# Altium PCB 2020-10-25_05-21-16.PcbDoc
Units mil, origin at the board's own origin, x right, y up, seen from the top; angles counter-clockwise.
Board outline 4000 x 2000 mil, 4 copper layers (Top Layer, MidLayer1, MidLayer2, Bottom Layer); 21 components, 14 nets, 69 pads, 67 vias.
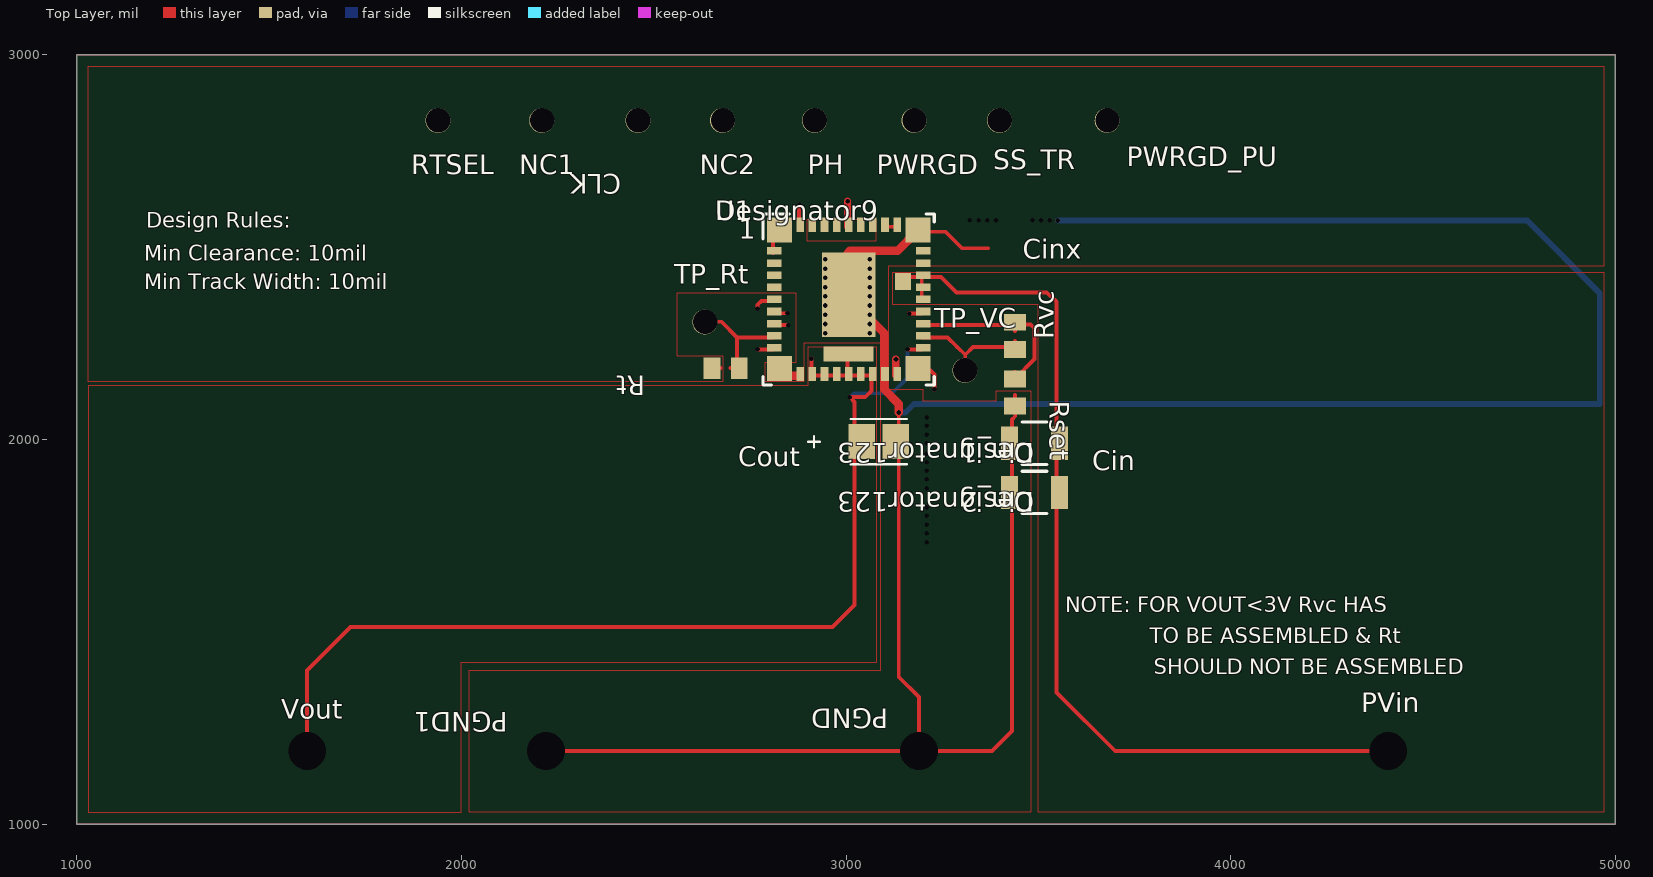
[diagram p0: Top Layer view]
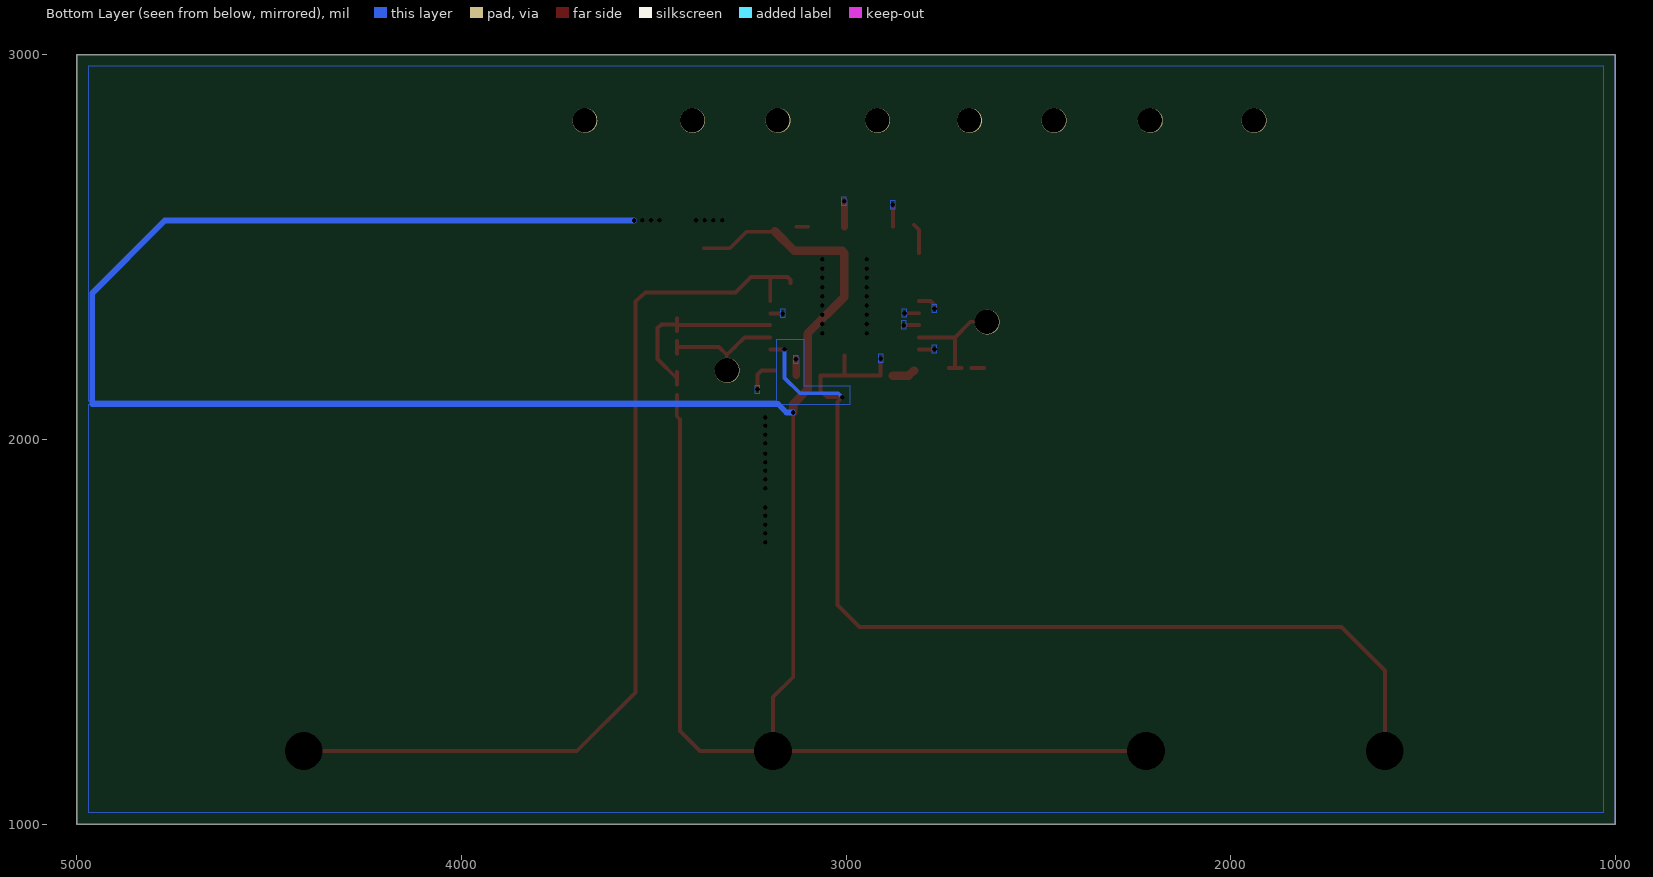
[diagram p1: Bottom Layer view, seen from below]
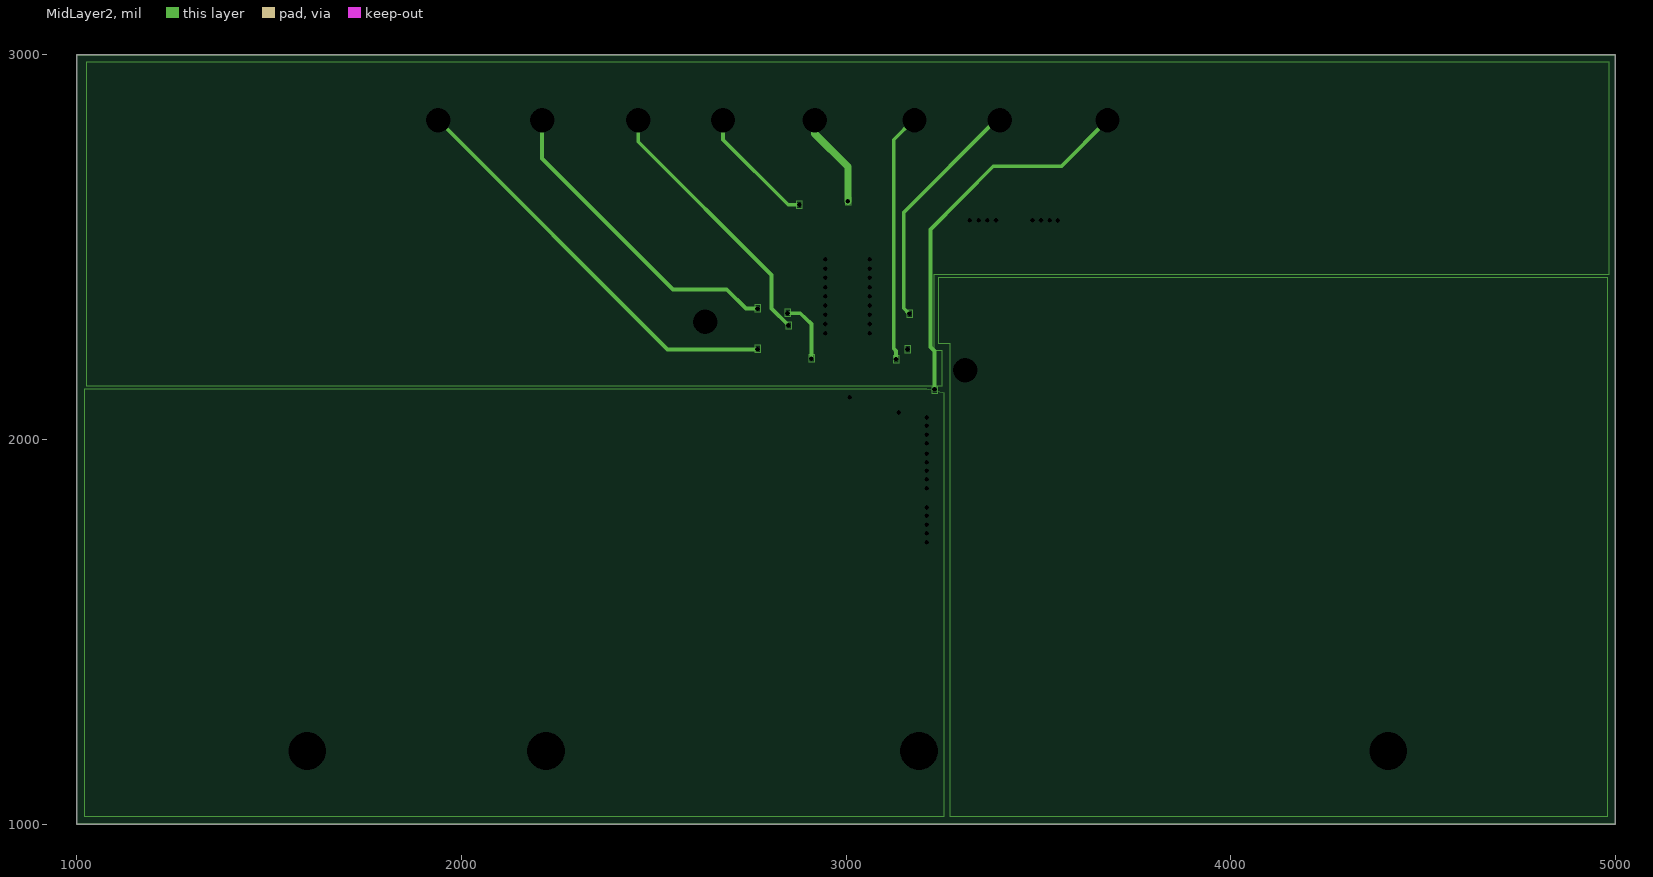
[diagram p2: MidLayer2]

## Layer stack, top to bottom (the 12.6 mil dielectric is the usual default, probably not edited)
Top Layer: signal copper 1.4
Dielectric: core 12.6, FR-4, Dk 4.8
MidLayer1: signal copper 1.4
Dielectric: prepreg 12.6, FR-4, Dk 4.8
MidLayer2: signal copper 1.4
Dielectric: core 12.6, FR-4, Dk 4.8
Bottom Layer: signal copper 1.4

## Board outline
1000,1000 5000,1000 5000,3000 1000,3000

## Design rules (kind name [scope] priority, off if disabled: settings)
PlaneConnect [All] p0: scope1count=1 scope1_0_kind=Board scope1_0_value=Board scope2count=1 scope2_0_kind=Board scope2_0_value=Board commentlength=0 planeconnectstyle=Direct reliefexpansion=20 reliefentries=4 reliefconductorwidth=10 reliefairgap=10
PlaneConnect [All] p1: planeconnectstyle=Direct reliefexpansion=20 reliefentries=4 reliefconductorwidth=10 reliefairgap=10
PolygonConnect [All] p0: scope1count=1 scope1_0_kind=Board scope1_0_value=Board scope2count=1 scope2_0_kind=Board scope2_0_value=Board commentlength=0 connectstyle=Direct reliefconductorwidth=10 reliefentries=4 polygonreliefangle="90 Angle"
PolygonConnect [All] p1: connectstyle=Direct reliefconductorwidth=10 reliefentries=4 polygonreliefangle="90 Angle"

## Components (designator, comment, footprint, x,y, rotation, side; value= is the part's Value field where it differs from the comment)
Cin_1 "" 1210_280 3490,1990 r180 top
Cin_2 "" 1210_280 3490,1862 r180 top
CLK "" TP-1502 2459,2829 r180 top
Cout "" 3528-21 3085,1994 r0 top
NC1 "" TP-1502 2209,2829 r0 top
NC2 "" TP-1502 2679,2829 r0 top
PGND "" TP-1502 3189,1189 r180 top
PGND1 "" TP-1502 2220,1189 r180 top
PH "" TP-1502 2918,2829 r0 top
PVin "" TP-1502 4409,1189 r0 top
PWRGD "" TP-1502 3177,2829 r0 top
PWRGD_PU "" TP-1502 3679,2829 r0 top
Rset "" 0805 3439,2122 r270 top
Rt "" 0805 2687,2185 r180 top
RTSEL "" TP-1502 1939,2829 r0 top
Rvc "" 0805 3439,2269 r90 top
SS_TR "" TP-1502 3399,2829 r0 top
TP_Rt "" TP-1502 2633,2305 r0 top
TP_VC "" TP-1502 3309,2179 r0 top
U1 "" RVQ0043A 3007,2364 r0 top
Vout "" TP-1502 1598,1189 r0 top

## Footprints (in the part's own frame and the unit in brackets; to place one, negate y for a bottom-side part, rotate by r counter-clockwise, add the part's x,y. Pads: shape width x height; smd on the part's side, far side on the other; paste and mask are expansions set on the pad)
0805 [mil]
  rect 44x57 smd: 1(-35.5,0) 2(35.5,0)
1210_280 [mm]
  rect 1.1x2.2 smd: 1(-1.65,0) 2(1.65,0)
  silkscreen extent -0.84,-1.4 0.84,1.4
3528-21 [mil]
  rect 69x91 smd: 1(-44.5,0) 2(44.5,0)
  silkscreen extent -183,-59 73,59
RVQ0043A [mm]
  rect 1.65x1.65 smd: 1(-4.575,4.575) 11(-4.575,-4.575) 21(4.575,-4.575) 31(4.575,4.575)
  rect 0.95x0.5 smd: 2(-4.925,3.2) 3(-4.925,2.4) 4(-4.925,1.6) 5(-4.925,0.8) 6(-4.925,0) 7(-4.925,-0.8) 8(-4.925,-1.6) 9(-4.925,-2.4) 10(-4.925,-3.2) 22(4.925,-3.2) 23(4.925,-2.4) 24(4.925,-1.6) 25(4.925,-0.8) 26(4.925,0) 27(4.925,0.8) 28(4.925,1.6) 29(4.925,2.4) 30(4.925,3.2)
  rect 0.5x0.95 smd: 12(-3.2,-4.925) 13(-2.4,-4.925) 14(-1.6,-4.925) 15(-0.8,-4.925) 16(0,-4.925) 17(0.8,-4.925) 18(1.6,-4.925) 19(2.4,-4.925) 20(3.2,-4.925) 32(3.2,4.925) 33(2.4,4.925) 34(1.6,4.925) 35(0.8,4.925) 36(0,4.925) 37(-0.8,4.925) 38(-1.6,4.925) 39(-2.4,4.925) 40(-3.2,4.925)
  rect 3.55x5.6 smd: 41(0,0.3)
  rect 1.05x1.12 smd: 42(3.575,1.187)
  rect 3.3x1 smd: 43(0,-3.6)
  silkscreen extent -5.65,-5.65 5.65,5.65
TP-1502 [mil]
  round 65 / inner round 0 / far side round 65 hole 32: 1(0,0)

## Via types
v1: diameter 0, hole 12, Top Layer to Bottom Layer, 53 vias
v2: diameter 0, hole 63, Top Layer to Bottom Layer, 10 vias
v3: diameter 0, hole 98, Top Layer to Bottom Layer, 4 vias

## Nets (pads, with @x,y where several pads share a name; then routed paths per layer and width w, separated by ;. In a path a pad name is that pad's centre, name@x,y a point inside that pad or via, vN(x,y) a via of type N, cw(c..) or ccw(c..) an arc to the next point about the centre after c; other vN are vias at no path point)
0: Cin_1.2 Cin_2.2 Cout.2 PGND1.1 PGND.1 Rset.2 Rt.2 U1.1 U1.2 U1.3 U1.4 U1.5 U1.11 U1.12 U1.19 U1.29 U1.30 U1.31 U1.32 U1.33 U1.41 | length 7717.2
  Top Layer w10: v3(2220,1190) v3(3190,1190) ; Rt.2@2641,2185.5 2674,2185.5 ; U1.2@2810,2485 2810,2545 U1.1@2823,2558 ; U1.33@3098,2553 U1.32@3129,2553 ; v1(3137,2070) 3137,1960 3137,1382 3190,1330 v3(3190,1190) ; U1.31@3184,2540 3259,2540 3302,2497 3370,2497 ; Rset.2@3439.5,2083 3439.5,2116 ; Rset.2@3440,2100 3440,2060 3432,2052 3432,1950 3432,1242 3380,1190 v3(3190,1190)
  Top Layer w22: U1.11@2823,2179 2837,2166 U1.12@2878,2166 ; v1(3137,2070) 3137,2092 3100,2130 3100,2275 3004,2371 3004,2484 3010,2490 3134,2490 3184,2540 U1.31@3185,2541
  Bottom Layer w15: v1(3137,2070) 3155,2070 3177,2092 4960,2092 4960,2380 4771,2569 v1(3551,2569)
  other v1: 3210,1733 3210,1756 3210,1778 3210,1801 3210,1823 3210,1873 3210,1896 3210,1918 3210,1941 3210,1963 3210,1990 3210,2012 3210,2035 3210,2057 2946,2276 3062,2276 2946,2300 3062,2300 2946,2324 3062,2324 2946,2348 3062,2348 2946,2372 3062,2372 2946,2396 3062,2396 2946,2420 3062,2420 2946,2444 3062,2444 2946,2468 3062,2468 3322,2570 3345,2570 3367,2570 3390,2570 3485,2570 3507,2570 3530,2570
4: Cin_1.1 Cin_2.1 PVin.1 U1.26 U1.27 U1.28 U1.42 | length 2444.2
  Top Layer w10: U1.42@3144,2406 3144,2414 3152,2422 U1.28@3197,2422 ; U1.26@3197,2360 3197,2391 U1.28@3197,2422 ; v3(4410,1190) 3700,1190 3547,1342 3547,2010 3547,2358 3522,2382 3370,2382 3287,2382 3247,2422 U1.28@3197,2422
5: Cout.1 U1.7 U1.13 U1.14 U1.15 U1.16 U1.17 U1.18 U1.22 U1.43 Vout.1 | length 3085.8
  Top Layer w10: v3(1599,1190) 1599,1399 1712,1512 2965,1512 3022,1569 3022,1960 3022,2097 v1(3010,2110) 3050,2110 3066,2126 3066,2166 U1.16@3004,2166 ; U1.7@2810,2328 v1(2848,2328) ; v1(2910,2210) 2910,2166 U1.16@3004,2166 ; U1.43@3004,2218 U1.16@3004,2166 ; v1(3160,2234) U1.22@3197,2234
  MidLayer2 w10: v1(2848,2328) 2881,2328 2910,2300 v1(2910,2210)
  Bottom Layer w10: v1(3010,2110) 3020,2120 3120,2120 3160,2160 v1(3160,2234)
7: Rset.1 Rvc.2 U1.24 | length 514.8
  Top Layer w10: U1.24@3197,2297 3437,2297 3440,2299 3480,2299 3490,2290 3490,2209 Rset.1@3440,2159 ; Rset.1@3439.5,2142 Rset.1@3439.5,2175 ; 3439.5,2282 Rvc.2@3439.5,2315
8: SS_TR.1 U1.25 | length 651.2
  Top Layer w10: v1(3164,2327) U1.25@3196,2327 ; U1.25@3197,2327 U1.25@3197,2328
  MidLayer2 w10: v1(3164,2327) 3150,2341 3150,2590 3390,2830 v2(3400,2830)
9: PWRGD.1 U1.20 | length 690.4
  Top Layer w19: U1.20@3129,2166 3129,2208
  MidLayer2 w10: v1(3130,2208) 3130,2230 3124,2236 3124,2779 3177,2832
  other v2: 3178,2830
10: PH.1 U1.34 U1.35 U1.36 U1.37 U1.38 U1.39 | length 315.6
  Top Layer w19: U1.36@3004,2553 3004,2619
  MidLayer2 w19: 2919,2833 2919,2795 3005,2709 v1(3005,2619)
  other v2: 2919,2830
12: NC2.1 U1.40 | length 375.7
  Top Layer w10: U1.40@2878,2553 v1(2878,2610)
  MidLayer2 w10: v2(2680,2830) 2680,2779 2850,2610 v1(2878,2610)
13: NC1.1 U1.6 | length 875.7
  Top Layer w10: v1(2770,2340) 2770,2350 2780,2360 U1.6@2810,2360
  MidLayer2 w10: v2(2210,2830) 2210,2730 2550,2390 2690,2390 2740,2340 v1(2770,2340)
14: Rvc.1 TP_VC.1 U1.23 | length 371.6
  Top Layer w10: U1.23@3197,2265 3264,2265 3310,2220 ; 3289,2240 3310,2220 ; v2(3310,2180) 3310,2220 ; Rvc.1@3439.5,2223 3439.5,2256 ; Rvc.1@3440,2240 3330,2240 3310,2220
15: RTSEL.1 U1.10 | length 1116.9
  Top Layer w10: v1(2770,2234) U1.10@2810,2234
  MidLayer2 w10: v2(1940,2830) 2536,2234 v1(2770,2234)
16: Rt.1 TP_Rt.1 U1.9 | length 305
  Top Layer w10: v2(2634,2306) 2676,2306 2717,2265 ; 2700,2185.5 Rt.1@2733,2185.5 ; Rt.1@2717,2186 2717,2264 2717,2265 ; U1.9@2810,2265 2717,2265
17: CLK.1 U1.8 | length 734.5
  Top Layer w10: U1.8@2810,2297 v1(2850,2297)
  MidLayer2 w10: v2(2460,2830) 2460,2774 2806,2427 2806,2340 v1(2850,2297)
18: PWRGD_PU.1 U1.21 | length 1087.2
  Top Layer w10: U1.21@3184,2179 3220,2179 3230,2169 v1(3230,2130)
  MidLayer2 w10: v1(3230,2130) 3230,2230 3220,2240 3220,2546 3383,2710 3560,2710 v2(3680,2830)

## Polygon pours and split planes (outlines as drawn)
9 on Bottom Layer " " (solid, pour order 16): 3124,2218 3137,2218 3137,2198 3124,2198
5 on Bottom Layer " " (solid, pour order 17): 2903,2221 2916,2221 2916,2201 2903,2201
17 on Bottom Layer " " (solid, pour order 18): 2844,2308 2857,2308 2857,2288 2844,2288
5 on Bottom Layer " " (solid, pour order 19): 2842,2339 2855,2339 2855,2319 2842,2319
18 on Bottom Layer " " (solid, pour order 20): 3224,2140 3237,2140 3237,2120 3224,2120
8 on Bottom Layer " " (solid, pour order 21): 3158,2338 3171,2338 3171,2318 3158,2318
10 on Bottom Layer " " (solid, pour order 22): 2999,2629 3012,2629 3012,2609 2999,2609
12 on Bottom Layer " " (solid, pour order 23): 2872,2620 2885,2620 2885,2600 2872,2600
13 on Bottom Layer " " (solid, pour order 24): 2764,2350 2777,2350 2777,2330 2764,2330
15 on Bottom Layer " " (solid, pour order 25): 2764,2245 2777,2245 2777,2225 2764,2225
0 on Bottom Layer " " (solid, pour order 40): 4970,2100 3180,2100 3180,2260 3110,2260 3110,2140 2990,2140 2990,2090 4970,2090 4970,1030 1030,1030 1030,2970 4970,2970
10 on Top Layer " " (solid, pour order 0): 3077,2515 2899,2515 2899,2572 3077,2572
4 on Top Layer " " (solid, pour order 1): 4970,1030 3500,1030 3500,2350 3121,2350 3121,2435 4970,2435
5 on Top Layer " " (solid, pour order 2): 1030,1030 2000,1030 2000,1420 3080,1420 3080,2240 2900,2240 2900,2140 1030,2140
0 on Top Layer " " (solid, pour order 38): 1030,2970 4970,2970 4970,2450 3110,2450 3110,2130 3200,2130 3200,2100 3390,2100 3390,2126 3480,2126 3480,1030 2020,1030 2020,1400 3090,1400 3090,2250 2890,2250 2890,2150 2790,2150 2790,2200 2870,2200 2870,2380 2560,2380 2560,2217 2680,2217 2680,2150 1030,2150
5 on MidLayer2 " " (solid, pour order 3): 2917,2221 2917,2200 2904,2200 2904,2221
13 on MidLayer2 " " (solid, pour order 4): 2777,2351 2777,2330 2764,2330 2764,2351
18 on MidLayer2 " " (solid, pour order 5): 3237,2140 3237,2119 3224,2119 3224,2140
8 on MidLayer2 " " (solid, pour order 6): 3172,2337 3172,2316 3159,2316 3159,2337
5 on MidLayer2 " " (solid, pour order 7): 3167,2245 3167,2224 3154,2224 3154,2245
9 on MidLayer2 " " (solid, pour order 8): 3137,2219 3137,2198 3124,2198 3124,2219
10 on MidLayer2 " " (solid, pour order 9): 3012,2630 3012,2609 2999,2609 2999,2630
12 on MidLayer2 " " (solid, pour order 10): 2885,2621 2885,2600 2872,2600 2872,2621
17 on MidLayer2 " " (solid, pour order 11): 2857,2306 2857,2287 2844,2287 2844,2306
5 on MidLayer2 " " (solid, pour order 12): 2855,2340 2855,2319 2842,2319 2842,2340
4 on MidLayer2 " " (solid, pour order 13): 4980,2420 3240,2420 3240,2250 3270,2250 3270,1020 4980,1020
5 on MidLayer2 " " (solid, pour order 14): 3255,2120 3210,2130 1020,2130 1020,1020 3255,1020
15 on MidLayer2 " " (solid, pour order 15): 2777,2246 2777,2225 2764,2225 2764,2246
5 on MidLayer1 " " (solid, pour order 26): 2916,2220 2916,2199 2903,2199 2903,2220
9 on MidLayer1 " " (solid, pour order 27): 3136,2218 3136,2197 3123,2197 3123,2218
5 on MidLayer1 " " (solid, pour order 28): 3166,2244 3166,2223 3153,2223 3153,2244
8 on MidLayer1 " " (solid, pour order 29): 3170,2337 3170,2316 3157,2316 3157,2337
10 on MidLayer1 " " (solid, pour order 30): 3011,2629 3011,2608 2998,2608 2998,2629
12 on MidLayer1 " " (solid, pour order 31): 2884,2620 2884,2599 2871,2599 2871,2620
17 on MidLayer1 " " (solid, pour order 32): 2856,2307 2856,2286 2843,2286 2843,2307
5 on MidLayer1 " " (solid, pour order 33): 2854,2338 2854,2317 2841,2317 2841,2338
13 on MidLayer1 " " (solid, pour order 34): 2776,2350 2776,2329 2763,2329 2763,2350
18 on MidLayer1 " " (solid, pour order 35): 3236,2140 3236,2119 3223,2119 3223,2140
15 on MidLayer1 " " (solid, pour order 36): 2777,2244 2777,2224 2764,2224 2764,2244
5 on MidLayer1 " " (solid, pour order 37): 3016,2120 3016,2099 3003,2099 3003,2120
0 on MidLayer2 " " (solid, pour order 39): 4984,2430 4984,2980 1024,2980 1024,2140 3250,2140 3250,2230 3230,2230 3230,2430
0 on MidLayer1 " " (solid, pour order 41): 4980,1020 4980,2980 1020,2980 1020,1020

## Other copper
Multi-Layer:
  the board outline again, w1

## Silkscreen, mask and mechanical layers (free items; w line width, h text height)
Top Overlay:
  text "Design Rules:" at 1180,2550 h40
  text "1" at 2721,2522 h50
  text "Cinx" at 3460,2470 h50
  text "Min Clearance: 10mil" at 1175,2465 h40
  text "Min Track Width: 10mil" at 1175,2390 h40
  text "Cin" at 3640,1920 h50
  text "NOTE: FOR VOUT<3V Rvc HAS" at 3570,1550 h40
  text "TO BE ASSEMBLED & Rt" at 3790,1470 h40
  text "SHOULD NOT BE ASSEMBLED" at 3800,1390 h40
